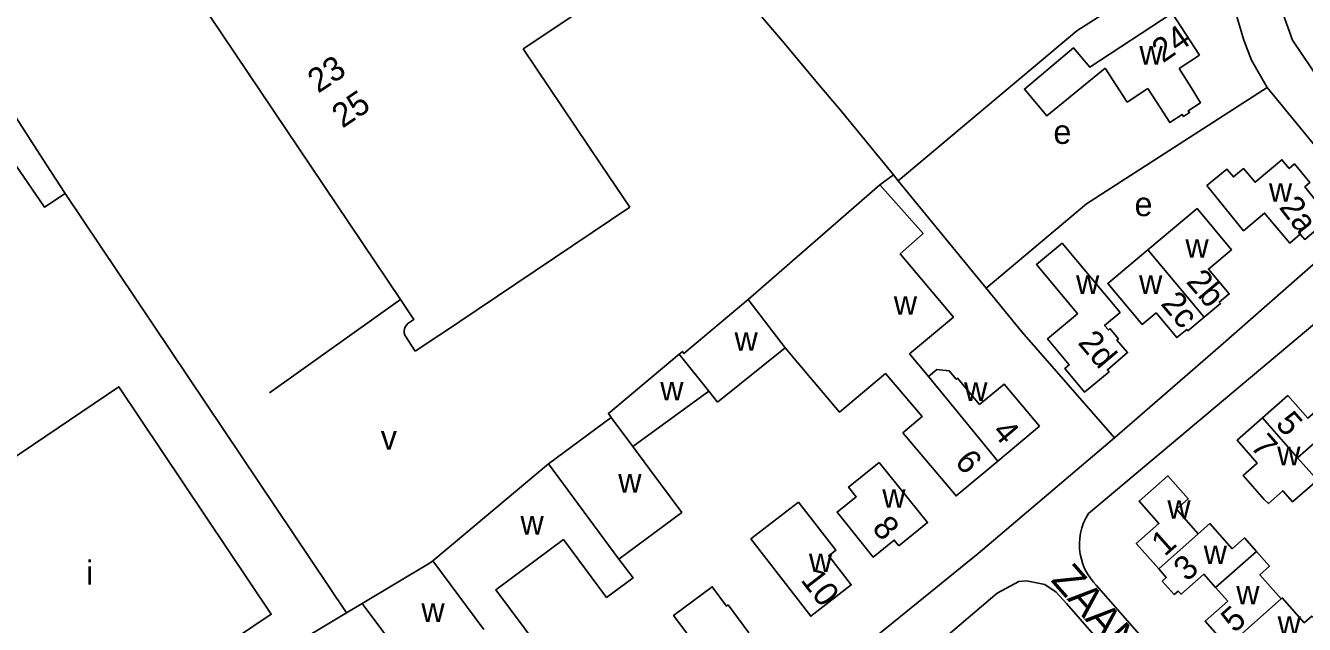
# Model space of a CAD drawing. Extents: x 156721 to 158827, y 386657 to 388950.
# Drawn here: x 157431.2 to 157643.5, y 387894.5 to 387994 of the extents above; entities that cross this region are included whole.
import ezdxf

# ---------------------------------------------------------------- set-up
doc = ezdxf.new("R2010")
doc.units = 0
for name, color, linetype in [('BLT_Basislijn', 7, 'Continuous'), ('BLT_Bebouwing', 7, 'Continuous'), ('BLT_Centroide', 7, 'Continuous'), ('BLT_Huisnummer', 7, 'Continuous'), ('BLT_Huisnummer_ tussenligend', 7, 'Continuous'), ('BLT_Huisnummer_reeks', 7, 'Continuous'), ('BLT_Onderverdeling_panden', 7, 'Continuous'), ('BLT_Straatnaam', 7, 'Continuous')]:
    doc.layers.add(name, color=color, linetype=linetype)

msp = doc.modelspace()

# ---------------------------------------------------------------- linework, layer by layer
at = {"layer": 'BLT_Basislijn'}
for p, q in [((157434.74, 387970.89), (157427.62, 387981.9)), ((157437.83, 387966.11), (157434.74, 387970.89)), ((157573.04, 387967.57), (157575.3, 387969.19)), ((157590.67, 387950.39), (157576.11, 387968.2)), ((157437.83, 387966.11), (157484.49, 387896.4)), ((157655.2, 387952.9), (157607.65, 387912.92)), ((157596.62, 387943.1), (157590.67, 387950.39)), ((157596.62, 387943.1), (157611.99, 387925.52)), ((157611.99, 387925.52), (157629.6, 387940.77)), ((157589.35, 387906.27), (157611.99, 387925.52)), ((157608.95, 387901.04), (157671.09, 387830.36))]:
    msp.add_line(p, q, dxfattribs=at)
for points in [[(157729.65, 387937.43), (157710.74, 387920.77), (157709.2, 387919.75), (157706.04, 387919.41), (157703.64, 387920.75), (157700, 387924.06), (157697.52, 387926.52), (157672, 387954.47), (157652.08, 387978.06), (157646.22, 387984.63), (157641.51, 387991.61), (157639.2, 387998.07), (157637.4, 388004.39), (157632.94, 388063.41)], [(157629.85, 388008.63), (157605.75, 387993.11), (157576.11, 387968.2)], [(157629.85, 388008.63), (157630.9, 388000.22), (157633.45, 387991.57), (157634.72, 387988.28)], [(157549.77, 387999.82), (157557.19, 387991.03), (157562.42, 387984.8)], [(157634.72, 387988.28), (157637.31, 387983.7)], [(157575.3, 387969.19), (157566.78, 387979.61), (157562.42, 387984.8)], [(157590.67, 387950.39), (157607.34, 387964.41), (157637.31, 387983.7)], [(157637.31, 387983.7), (157650.8, 387967.3), (157652.08, 387965.57)], [(157429.55, 387970.89), (157434.4, 387963.82), (157437.83, 387966.11)], [(157576.11, 387968.2), (157575.3, 387969.19)], [(157652.08, 387965.57), (157652.48, 387964.89), (157652.71, 387963.62), (157652.74, 387962.59), (157652.21, 387961.34), (157651.87, 387960.61), (157650.81, 387959.45), (157629.6, 387940.77)], [(157493.49, 387948.51), (157471.74, 387932.97)], [(157607.65, 387912.92), (157607.22, 387912.15), (157606.86, 387911.36), (157606.57, 387910.53), (157606.36, 387909.68), (157606.22, 387908.81), (157606.17, 387907.94), (157606.2, 387907.07), (157606.3, 387906.2), (157606.49, 387905.34), (157606.75, 387904.5), (157607.09, 387903.7), (157607.5, 387902.92), (157607.98, 387902.19), (157608.52, 387901.5), (157608.95, 387901.04)], [(157589.35, 387906.27), (157534.05, 387861.36), (157532.64, 387860.36)], [(157598.1, 387799.07), (157643.84, 387839.41), (157647.1, 387842.84), (157647.76, 387845.18), (157647.71, 387846.88), (157647.26, 387848.11), (157645.66, 387850.18), (157604.01, 387897.98), (157602.32, 387899.85), (157600.43, 387901.14), (157597.4, 387901.74), (157596.12, 387901.62), (157592.52, 387899.67), (157572.88, 387882.96)]]:
    msp.add_lwpolyline(points, dxfattribs=at)
at = {"layer": 'BLT_Bebouwing'}
for p, q in [((157621.59, 387996.09), (157626.12, 387989.07)), ((157526.79, 387970.89), (157513.82, 387990.16)), ((157622.71, 387986.88), (157626.12, 387989.07)), ((157610.44, 387986.95), (157614.1, 387981.31)), ((157624.71, 387983.74), (157622.71, 387986.88)), ((157614.1, 387981.31), (157617.52, 387983.54)), ((157617.52, 387983.54), (157619.56, 387980.4)), ((157531.52, 387963.86), (157526.79, 387970.89)), ((157573.04, 387967.57), (157551.21, 387948.52)), ((157495.94, 387939.91), (157500, 387942.64)), ((157494.3, 387942.39), (157495.94, 387939.91)), ((157546.1, 387931.45), (157557.33, 387940.44)), ((157581.11, 387935.68), (157577.95, 387939.44)), ((157544.68, 387933.24), (157532.05, 387924.05)), ((157544.68, 387933.24), (157546.1, 387931.45)), ((157528.45, 387928.91), (157518.05, 387921.18)), ((157534.86, 387920.26), (157532.05, 387924.05)), ((157518.05, 387921.18), (157498.86, 387905.05)), ((157484.49, 387896.4), (157487.14, 387897.99)), ((157475.95, 387891.28), (157484.49, 387896.4))]:
    msp.add_line(p, q, dxfattribs=at)
for points in [[(157513.82, 387990.16), (157528.53, 388000), (157530.4, 388001.25), (157514.42, 388025.09)], [(157493.49, 387948.51), (157449.18, 388014.51)], [(157610.44, 387986.95), (157600.77, 387979), (157597.04, 387983.45), (157605.21, 387990.3), (157607.88, 387987.12), (157621.59, 387996.09)], [(157619.56, 387980.4), (157621.18, 387977.9), (157623.23, 387979.22), (157623.45, 387978.89), (157624.45, 387979.54), (157624.24, 387979.87), (157626.27, 387981.19), (157624.71, 387983.74)], [(157577.95, 387939.44), (157585.25, 387945.58), (157576.43, 387956.08), (157580.23, 387959.45), (157573.04, 387967.57)], [(157500, 387942.64), (157500.09, 387942.7), (157531.52, 387963.86)], [(157626.89, 387945.55), (157629.59, 387947.82), (157629.37, 387948.06), (157631.03, 387949.43), (157627.59, 387953.54), (157631.43, 387956.76), (157625.71, 387963.6), (157617.51, 387956.73)], [(157611.23, 387943.65), (157610.97, 387943.43), (157610.34, 387944.19), (157612.93, 387946.34), (157603.31, 387957.85), (157599.04, 387954.29), (157605.75, 387946.27), (157605.87, 387946.12), (157600.85, 387941.94), (157604.46, 387937.63), (157603.73, 387937.02), (157607.02, 387933.08), (157611.1, 387936.49), (157610.81, 387936.83), (157614.15, 387939.66), (157612.38, 387941.76), (157612.65, 387941.96), (157611.23, 387943.65)], [(157617.51, 387956.73), (157610.86, 387951.17), (157616.59, 387944.34), (157618.9, 387946.26), (157622.33, 387942.17), (157623.97, 387943.52), (157624.18, 387943.28), (157626.89, 387945.55)], [(157494.72, 387944.48), (157495.69, 387945.15), (157493.49, 387948.51)], [(157551.21, 387948.52), (157540.51, 387939.5), (157540.26, 387939.86), (157539.76, 387939.42)], [(157494.72, 387944.48), (157494.46, 387944.25), (157494.26, 387943.96), (157494.12, 387943.63), (157494.07, 387943.28), (157494.09, 387942.93), (157494.19, 387942.59), (157494.3, 387942.39)], [(157557.33, 387940.44), (157566.36, 387929.75), (157573.98, 387936.19), (157580.06, 387929.05), (157576.87, 387926.33), (157585.71, 387915.85), (157592.62, 387921.65)], [(157539.76, 387939.42), (157527.99, 387929.57), (157528.45, 387928.91)], [(157599.52, 387927.44), (157593.66, 387934.44), (157589.6, 387931.05), (157585.94, 387935.42), (157585.72, 387935.23), (157584.56, 387936.62), (157582.48, 387936.87), (157581.11, 387935.68)], [(157409.42, 387908.81), (157414.45, 387912.18), (157410.44, 387918.15), (157424.45, 387927.56), (157428.45, 387921.62), (157446.74, 387933.97), (157472.03, 387896.19), (157453.77, 387883.92)], [(157646.36, 387930.74), (157644.1, 387928.75), (157640.76, 387932.54), (157636.55, 387928.82)], [(157636.55, 387928.82), (157632.34, 387925.11), (157635.68, 387921.32), (157633.35, 387919.27), (157636.86, 387915.27), (157637.54, 387914.59), (157639.92, 387916.7), (157641.55, 387914.86), (157645.66, 387918.49), (157642.38, 387922.2)], [(157592.62, 387921.65), (157599.52, 387927.44)], [(157650.49, 387926.04), (157648.14, 387923.96), (157646.49, 387925.83), (157642.38, 387922.2)], [(157576.17, 387907.57), (157575.42, 387908.51), (157571.92, 387905.7), (157565.94, 387913.17), (157569.13, 387915.73), (157567.84, 387917.33), (157572.95, 387921.43)], [(157572.95, 387921.43), (157580.96, 387911.42), (157576.17, 387907.57)], [(157529.73, 387905.37), (157540.16, 387913.1), (157534.86, 387920.26)], [(157625.9, 387909.58), (157622.3, 387913.66), (157624.22, 387915.36), (157620.84, 387919.19), (157616.08, 387914.99), (157619.37, 387911.25), (157615.61, 387907.93), (157619.33, 387903.72)], [(157559.56, 387914.83), (157565.74, 387906.84), (157564.55, 387905.92), (157568.3, 387901.06), (157561.57, 387895.86), (157551.64, 387908.71), (157559.56, 387914.83)], [(157625.9, 387909.58), (157627.81, 387911.26), (157631.5, 387907.07), (157633.55, 387908.88), (157635.56, 387906.6)], [(157529.73, 387905.37), (157532.07, 387902.23), (157527.69, 387898.97), (157520.53, 387908.6), (157509.29, 387900.24), (157516.43, 387890.66), (157512.01, 387887.37)], [(157635.56, 387906.6), (157637.71, 387904.17), (157636.12, 387902.76), (157639.66, 387898.74)], [(157487.14, 387897.99), (157498.38, 387904.74), (157498.86, 387905.05)], [(157619.33, 387903.72), (157620.59, 387902.29), (157619.92, 387901.7), (157621.91, 387899.45), (157622.58, 387900.04), (157623.04, 387899.51), (157626.82, 387902.84), (157628.77, 387900.64)], [(157539.81, 387891.79), (157541.17, 387892.8), (157538.8, 387895.99), (157545.21, 387900.76), (157547.6, 387897.55), (157547.84, 387897.73), (157551.3, 387893.1)], [(157628.77, 387900.64), (157630.79, 387898.35), (157627.04, 387895.04), (157630.73, 387890.86)], [(157639.66, 387898.74), (157639.84, 387898.9), (157643.48, 387894.77), (157644.74, 387895.88), (157646.86, 387893.55)]]:
    msp.add_lwpolyline(points, dxfattribs=at)
msp.add_lwpolyline([(157627.34, 387967.41), (157633.43, 387959.93), (157633.43, 387959.93), (157636.9, 387962.84), (157641.07, 387957.86), (157642.83, 387959.34), (157643.56, 387958.48), (157647.63, 387961.87), (157645.2, 387964.78), (157645.41, 387964.97), (157643.56, 387967.21), (157644.42, 387967.95), (157641.86, 387971.01), (157641, 387970.28), (157639.78, 387971.72), (157635.33, 387967.99), (157633.42, 387970.25), (157631.73, 387968.85), (157630.65, 387970.13)], close=True, dxfattribs=at)
at = {"layer": 'BLT_Onderverdeling_panden'}
for p, q in [((157617.51, 387956.73), (157626.89, 387945.55)), ((157557.33, 387940.44), (157551.21, 387948.52)), ((157539.76, 387939.42), (157544.68, 387933.24)), ((157581.11, 387935.68), (157592.62, 387921.65)), ((157532.05, 387924.05), (157528.45, 387928.91)), ((157636.55, 387928.82), (157642.38, 387922.2)), ((157518.05, 387921.18), (157529.73, 387905.37)), ((157619.33, 387903.72), (157625.9, 387909.58)), ((157635.56, 387906.6), (157628.77, 387900.64)), ((157498.86, 387905.05), (157507.31, 387893.66)), ((157496.41, 387885.58), (157487.14, 387897.99)), ((157630.73, 387890.86), (157639.66, 387898.74))]:
    msp.add_line(p, q, dxfattribs=at)

# ---------------------------------------------------------------- texts
at = {"layer": 'BLT_Centroide'}
for s, p in [('w', (157616.13, 387987.53)), ('e', (157601.85, 387974.35)), ('w', (157637.62, 387964.75)), ('e', (157615.32, 387962.34)), ('w', (157623.76, 387955.43)), ('w', (157605.61, 387949.43)), ('w', (157616.07, 387949.43)), ('w', (157575.36, 387945.95)), ('w', (157548.92, 387939.97)), ('w', (157536.59, 387931.72)), ('w', (157587.04, 387931.64)), ('v', (157490.21, 387923.55)), ('w', (157639, 387920.95)), ('w', (157529.62, 387916.41)), ('w', (157573.45, 387913.88)), ('w', (157620.77, 387912.06)), ('w', (157513.39, 387909.44)), ('w', (157626.8, 387904.53)), ('i', (157441.29, 387901.1)), ('w', (157561.27, 387903.2)), ('w', (157632.2, 387897.83)), ('w', (157496.94, 387894.92)), ('w', (157639.07, 387892.78))]:
    msp.add_text(s, height=4, dxfattribs=at).set_placement(p)
at = {"layer": 'BLT_Huisnummer'}
for s, rotation, p in [('24', 34.9615, (157620.02, 387987.7)), ('2a', 307.6629, (157639.18, 387963.78)), ('2b', 310.2254, (157623.74, 387951.4)), ('2c', 310.2254, (157619.52, 387947.73)), ('2d', 310.2254, (157605.77, 387941.26)), ('4', 310.2254, (157591.53, 387926.42)), ('7', 311.2929, (157634.39, 387923.98)), ('6', 310.2254, (157585.33, 387921.45)), ('8', 310.2254, (157571.6, 387910.43)), ('1', 41.4374, (157620.32, 387905.69)), ('10', 307.6988, (157559.78, 387901.86)), ('5', 41.4374, (157631.89, 387892.97))]:
    msp.add_text(s, height=4, rotation=rotation, dxfattribs=at).set_placement(p)
at = {"layer": 'BLT_Huisnummer_ tussenligend'}
for s, rotation, p in [('5', 311.2929, (157638.57, 387927.72)), ('3', 41.4374, (157624, 387901.49))]:
    msp.add_text(s, height=4, rotation=rotation, dxfattribs=at).set_placement(p)
at = {"layer": 'BLT_Huisnummer_reeks'}
for s, p in [('23', (157479.81, 387982.67)), ('25', (157483.84, 387976.87))]:
    msp.add_text(s, height=4, rotation=33.9476, dxfattribs=at).set_placement(p)
at = {"layer": 'BLT_Straatnaam'}
msp.add_text('ZAANSTRAAT', height=5, rotation=311.3927, dxfattribs=at).set_placement((157601.3, 387901.78))

doc.saveas('drawing.dxf')
